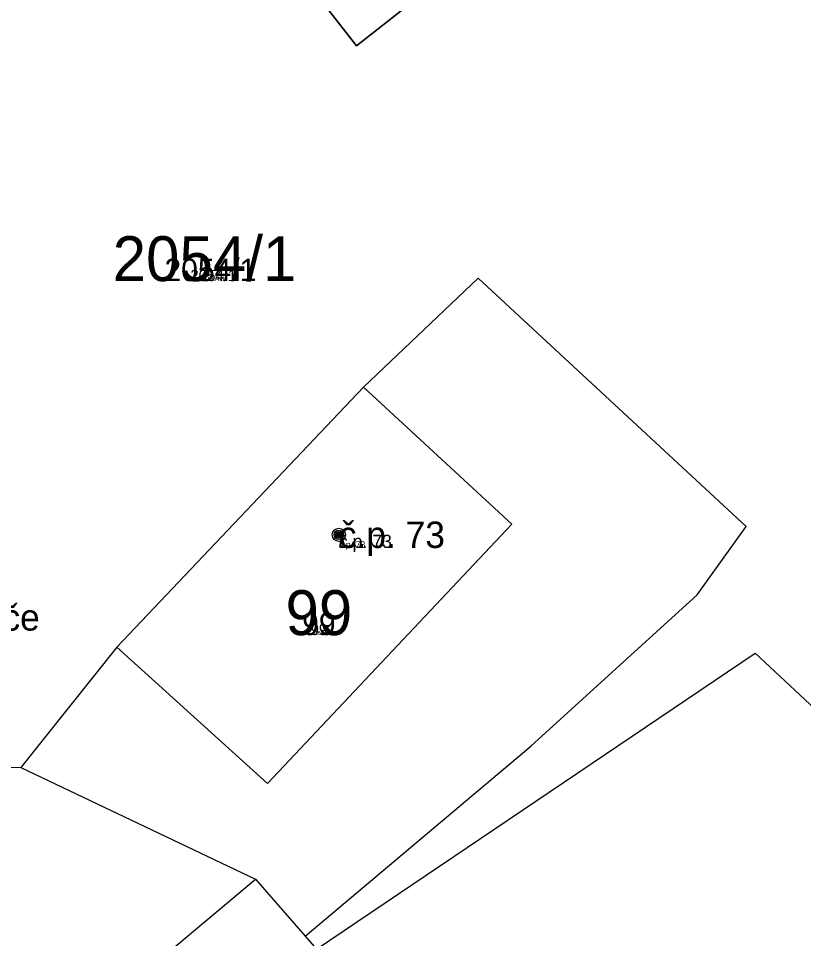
# Model space of a CAD drawing. Extents: x -744652 to -739090, y -980828 to -975855.
# Drawn here: x -742844.09 to -742814.36, y -978620.95 to -978586.09 of the extents above; entities that cross this region are included whole.
import ezdxf

# ---------------------------------------------------------------- set-up
doc = ezdxf.new("R2010")
doc.units = 0
for name, color, linetype in [('KAT_02_hranice parcel', 7, 'Continuous'), ('KAT_03_1000_st čísla parcelní', 7, 'Continuous'), ('KAT_03_1000_čísla parcelní', 7, 'Continuous'), ('KAT_03_1000_čísla popisná', 7, 'Continuous'), ('KAT_03_100_st čísla parcelní', 7, 'Continuous'), ('KAT_03_100_čísla parcelní', 7, 'Continuous'), ('KAT_03_100_čísla popisná', 7, 'Continuous'), ('KAT_03_250_st čísla parcelní', 7, 'Continuous'), ('KAT_03_250_čísla parcelní', 7, 'Continuous'), ('KAT_03_250_čísla popisná', 7, 'Continuous'), ('KAT_03_500_st čísla parcelní', 7, 'Continuous'), ('KAT_03_500_čísla parcelní', 7, 'Continuous'), ('KAT_03_500_čísla popisná', 7, 'Continuous'), ('KAT_04_vnitřní kresba', 7, 'Continuous'), ('KAT_07_1000_značky budov', 7, 'Continuous'), ('KAT_07_100_značky budov', 7, 'Continuous'), ('KAT_07_500_značky budov', 7, 'Continuous'), ('KAT_14_plocha_budovy', 7, 'Continuous')]:
    doc.layers.add(name, color=color, linetype=linetype)

msp = doc.modelspace()

# ---------------------------------------------------------------- linework, layer by layer
at = {"layer": 'KAT_02_hranice parcel'}
for p, q in [((-742848.8, -978614.39), (-742844, -978614.47)), ((-742844, -978614.47), (-742835.12, -978618.7)), ((-742835.12, -978618.7), (-742833.24, -978620.85)), ((-742833.24, -978620.85), (-742832.81, -978621.35))]:
    msp.add_line(p, q, dxfattribs=at)
for points in [[(-742828.82, -978579.84), (-742826.25, -978583.15), (-742831.29, -978587.13), (-742833.85, -978583.83)], [(-742833.24, -978620.85), (-742824.69, -978613.66), (-742818.4, -978607.92), (-742816.54, -978605.34), (-742826.69, -978595.93), (-742831.03, -978600.06)], [(-742831.03, -978600.06), (-742840.37, -978609.91), (-742844, -978614.47)], [(-742832.81, -978621.35), (-742816.2, -978610.13), (-742805.61, -978620.02), (-742804.17, -978634.55), (-742832.81, -978621.35)], [(-742816.31, -978640.22), (-742835.12, -978656.02), (-742853.77, -978634.34), (-742835.12, -978618.7)]]:
    msp.add_lwpolyline(points, dxfattribs=at)
at = {"layer": 'KAT_03_1000_čísla popisná'}
msp.add_circle((-742831.96, -978605.65), 0.25, dxfattribs=at)
msp.add_circle((-742831.96, -978605.65), 0.25, dxfattribs=at)
at = {"layer": 'KAT_03_100_čísla popisná'}
msp.add_circle((-742831.96, -978605.65), 0.025, dxfattribs=at)
msp.add_circle((-742831.96, -978605.65), 0.025, dxfattribs=at)
at = {"layer": 'KAT_03_250_čísla popisná'}
msp.add_circle((-742831.96, -978605.65), 0.0625, dxfattribs=at)
msp.add_circle((-742831.96, -978605.65), 0.0625, dxfattribs=at)
at = {"layer": 'KAT_03_500_čísla popisná'}
msp.add_circle((-742831.96, -978605.65), 0.125, dxfattribs=at)
msp.add_circle((-742831.96, -978605.65), 0.125, dxfattribs=at)
at = {"layer": 'KAT_04_vnitřní kresba'}
for p, q in [((-742831.03, -978600.06), (-742825.41, -978605.25)), ((-742834.66, -978615.07), (-742825.41, -978605.25)), ((-742840.37, -978609.91), (-742834.66, -978615.07))]:
    msp.add_line(p, q, dxfattribs=at)
at = {"layer": 'KAT_07_1000_značky budov'}
msp.add_circle((-742831.967, -978605.649), 0.175, dxfattribs=at)
at = {"layer": 'KAT_07_100_značky budov'}
msp.add_circle((-742831.961, -978605.65), 0.0175, dxfattribs=at)
at = {"layer": 'KAT_07_500_značky budov'}
for centre, radius in [((-742831.963, -978605.65), 0.0875), ((-742831.962, -978605.65), 0.0438)]:
    msp.add_circle(centre, radius, dxfattribs=at)
at = {"layer": 'KAT_14_plocha_budovy'}
for points in [[(-742833.85, -978583.83), (-742831.29, -978587.13), (-742826.25, -978583.15), (-742828.82, -978579.84)], [(-742840.37, -978609.91), (-742834.66, -978615.07), (-742825.41, -978605.25), (-742831.03, -978600.06)]]:
    msp.add_lwpolyline(points, close=True, dxfattribs=at)

# ---------------------------------------------------------------- texts
at = {"layer": 'KAT_03_1000_st čísla parcelní'}
msp.add_text('99', height=1.7, dxfattribs=at).set_placement((-742833.982, -978609.45))
at = {"layer": 'KAT_03_1000_čísla parcelní'}
msp.add_text('2054/1', height=1.7, dxfattribs=at).set_placement((-742840.525, -978596.04))
at = {"layer": 'KAT_03_1000_čísla popisná'}
for s, height, p in [('č.p. 73', 1, (-742831.96, -978606.15)), ('bez čp/če', 1, (-742849.01, -978609.28)), ('99', 0.017, (-742832.73, -978609.45))]:
    msp.add_text(s, height=height, dxfattribs=at).set_placement(p)
at = {"layer": 'KAT_03_100_st čísla parcelní'}
msp.add_text('99', height=0.17, dxfattribs=at).set_placement((-742832.844, -978609.45))
at = {"layer": 'KAT_03_100_čísla parcelní'}
msp.add_text('2054/1', height=0.17, dxfattribs=at).set_placement((-742836.995, -978596.04))
at = {"layer": 'KAT_03_100_čísla popisná'}
for s, height, p in [('č.p. 73', 0.1, (-742831.96, -978606.15)), ('99', 0.0017, (-742832.718, -978609.45))]:
    msp.add_text(s, height=height, dxfattribs=at).set_placement(p)
at = {"layer": 'KAT_03_250_st čísla parcelní'}
msp.add_text('99', height=0.425, dxfattribs=at).set_placement((-742833.033, -978609.45))
at = {"layer": 'KAT_03_250_čísla parcelní'}
msp.add_text('2054/1', height=0.425, dxfattribs=at).set_placement((-742837.584, -978596.04))
at = {"layer": 'KAT_03_250_čísla popisná'}
for s, height, p in [('č.p. 73', 0.25, (-742831.96, -978606.15)), ('99', 0.00425, (-742832.72, -978609.45))]:
    msp.add_text(s, height=height, dxfattribs=at).set_placement(p)
at = {"layer": 'KAT_03_500_st čísla parcelní'}
msp.add_text('99', height=0.85, dxfattribs=at).set_placement((-742833.35, -978609.45))
at = {"layer": 'KAT_03_500_čísla parcelní'}
msp.add_text('2054/1', height=0.85, dxfattribs=at).set_placement((-742838.564, -978596.04))
at = {"layer": 'KAT_03_500_čísla popisná'}
for s, height, p in [('č.p. 73', 0.5, (-742831.96, -978606.15)), ('99', 0.0085, (-742832.723, -978609.45))]:
    msp.add_text(s, height=height, dxfattribs=at).set_placement(p)

doc.saveas('drawing.dxf')
